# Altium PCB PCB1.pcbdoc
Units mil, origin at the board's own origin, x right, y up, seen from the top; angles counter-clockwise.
Board outline 4979.02 x 1805 mil, 2 copper layers (Top Layer, Bottom Layer); 6 components, 11 nets, 70 pads, 4 vias.
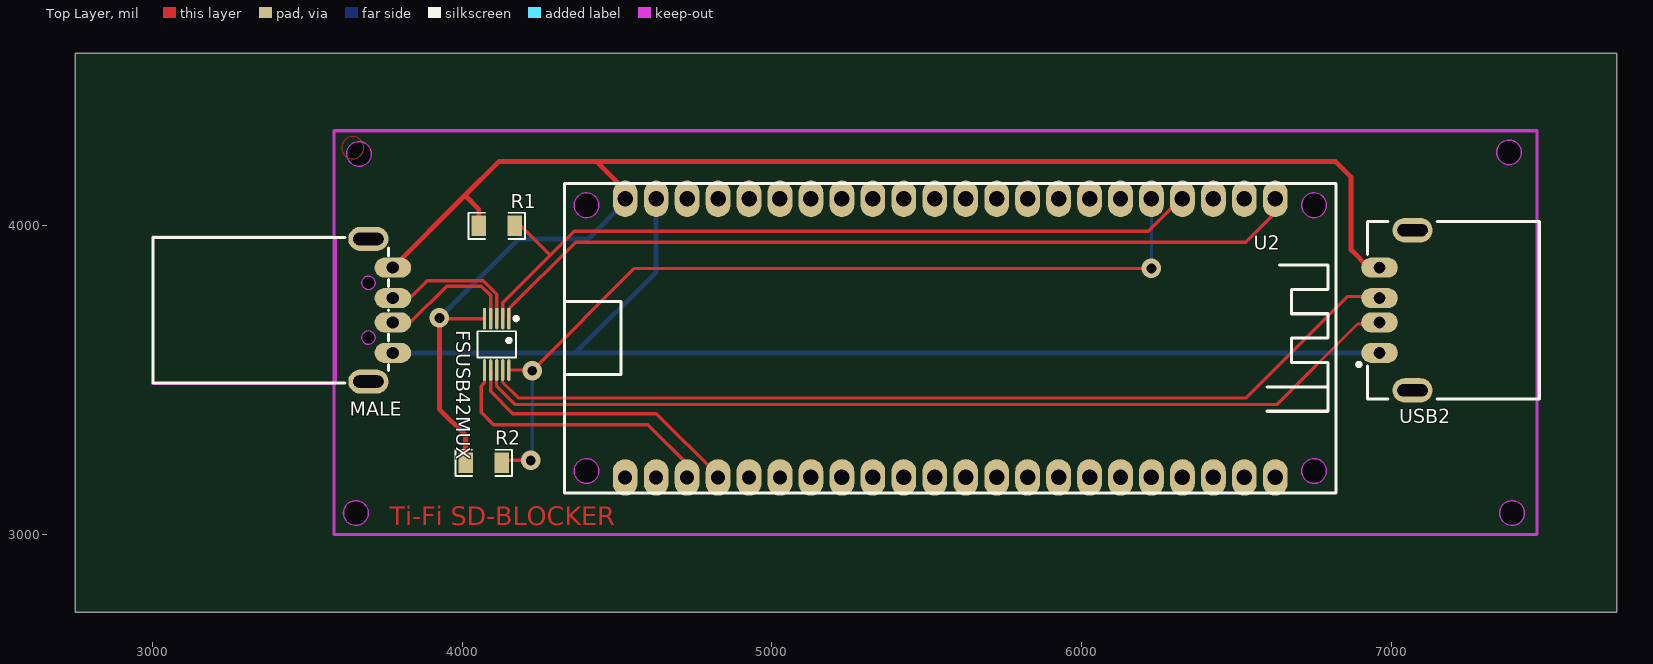
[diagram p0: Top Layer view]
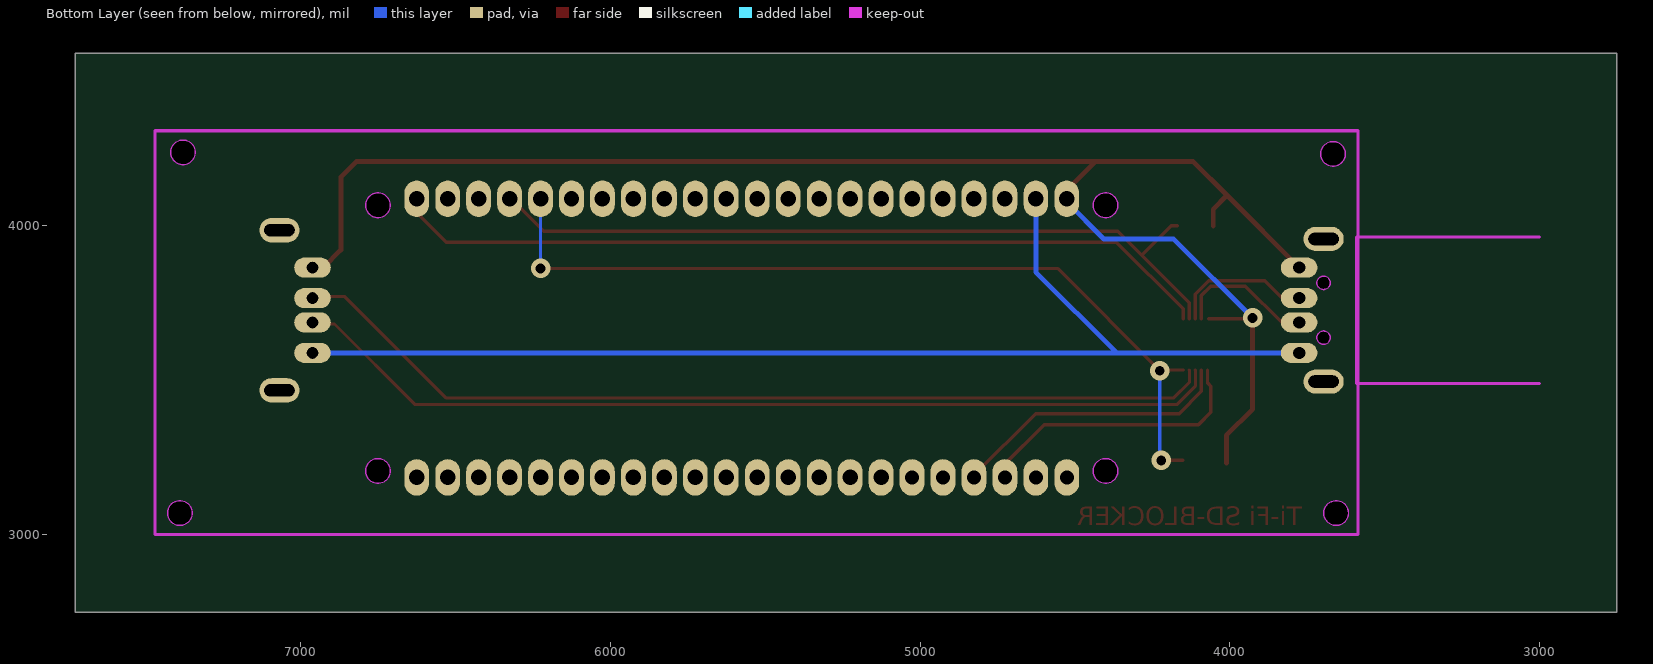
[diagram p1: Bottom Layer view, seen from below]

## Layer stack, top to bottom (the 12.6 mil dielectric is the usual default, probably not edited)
Top Layer: signal copper (thickness not stored)
Dielectric: dielectric 12.6, FR-4, Dk 4.8
Bottom Layer: signal copper (thickness not stored)

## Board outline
7729.02,2750 2750,2750 2750,4555 7729.02,4555
cut-out: 3706.22,4230 cw(c3666.22,4230) 3626.22,4230 cw(c3666.22,4230)
cut-out: 3696.22,3070 cw(c3656.22,3070) 3616.22,3070 cw(c3656.22,3070)
cut-out: 7431.22,3070 cw(c7391.22,3070) 7351.22,3070 cw(c7391.22,3070)
cut-out: 7421.22,4235 cw(c7381.22,4235) 7341.22,4235 cw(c7381.22,4235)

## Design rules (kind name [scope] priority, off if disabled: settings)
BoardOutlineClearance copperThickness1oz [All] p0: genericclearance=10 ignorepadtopadclearanceinfootprint=FALSE except(0: Arc-SplitContinuation Track-SplitContinuation SMDPad-SplitContinuation THPad-SplitContinuation Via-SplitContinuation Fill-SplitContinuation Poly-SplitContinuation Region-SplitContinuation Text-SplitContinuation; 7.9: Track-OutlineEdge SMDPad-OutlineEdge THPad-OutlineEdge Via-OutlineEdge Fill-OutlineEdge Region-OutlineEdge Poly-OutlineEdge Text-OutlineEdge Track-CutoutEdge SMDPad-CutoutEdge THPad-CutoutEdge Via-CutoutEdge Fill-CutoutEdge Region-CutoutEdge)
BoardOutlineClearance copperThickness2oz [All] p0: genericclearance=10 ignorepadtopadclearanceinfootprint=FALSE except(0: Arc-SplitContinuation Track-SplitContinuation SMDPad-SplitContinuation THPad-SplitContinuation Via-SplitContinuation Fill-SplitContinuation Poly-SplitContinuation Region-SplitContinuation Text-SplitContinuation; 6: SMDPad-CutoutEdge THPad-CutoutEdge Via-CutoutEdge Fill-CutoutEdge Region-CutoutEdge; 11.8: Track-OutlineEdge SMDPad-OutlineEdge THPad-OutlineEdge Via-OutlineEdge Fill-OutlineEdge Region-OutlineEdge Poly-OutlineEdge Text-OutlineEdge Track-CutoutEdge)
Clearance copperThickness1oz [(InNet('$1N2926') OR InNet('$1N2770') OR InNet('$1N2815') OR InNet('$1N3095') OR InNet('$1N3264') OR InNet('$1N3111') OR InNet('$1N3122') OR InNet('$1N2863') OR InNet('$1N3580') OR InNet('$1N3681') OR InNet('$1N5589'))] p1: gap=7 ignorepadtopadclearanceinfootprint=FALSE except(7.9: Track-Track Track-SMDPad SMDPad-SMDPad Track-THPad SMDPad-THPad THPad-THPad Track-Via SMDPad-Via THPad-Via Via-Via Track-Fill SMDPad-Fill THPad-Fill Via-Fill Fill-Fill Track-Region SMDPad-Region THPad-Region Via-Region Fill-Region Region-Region Track-Poly SMDPad-Poly THPad-Poly Via-Poly Fill-Poly Region-Poly Poly-Poly Track-Text SMDPad-Text THPad-Text Via-Text Fill-Text Region-Text Poly-Text Text-Text Track-Sheet SMDPad-Sheet THPad-Sheet Via-Sheet Fill-Sheet Region-Sheet Poly-Sheet Text-Sheet Track-Hole SMDPad-Hole THPad-Hole Via-Hole Fill-Hole Region-Hole Poly-Hole Text-Hole Sheet-Hole)
Clearance copperThickness2oz [All] p1: gap=7 ignorepadtopadclearanceinfootprint=FALSE except(6: Track-SMDPad SMDPad-SMDPad Track-THPad SMDPad-THPad THPad-THPad Track-Via SMDPad-Via THPad-Via Via-Via Track-Fill SMDPad-Fill THPad-Fill Via-Fill Fill-Fill SMDPad-Region THPad-Region Via-Region Fill-Region Region-Region Track-Poly SMDPad-Poly THPad-Poly Via-Poly Fill-Poly Poly-Poly Track-Text SMDPad-Text THPad-Text Via-Text Fill-Text Region-Text Poly-Text Text-Text; 6.9: Track-Hole SMDPad-Hole THPad-Hole Via-Hole Fill-Hole Region-Hole Poly-Hole Text-Hole Sheet-Hole; 8: Track-Track; 11.8: Track-Region Region-Poly Track-Sheet SMDPad-Sheet THPad-Sheet Via-Sheet Fill-Sheet Region-Sheet Poly-Sheet Text-Sheet)
DiffPairsRouting differentialPair [All] p1: maxuncoupledlength=10 minlimit=5.9843 maxlimit=5.9843 mostfreqgap=5.9843 toplayer_minwidth=5 toplayer_prefwidth=10 toplayer_maxwidth=100 bottomlayer_minwidth=5 bottomlayer_prefwidth=10 bottomlayer_maxwidth=100
PasteMaskExpansion pasteMaskExpansion [All] p1: expansion=0
PlaneConnect innerPlane [All] p1: planeconnectstyle=Relief reliefexpansion=20 reliefentries=4 reliefconductorwidth=10 reliefairgap=10
PolygonConnect copperRegion [All] p1: connectstyle=Relief reliefentries=4 reliefconductorwidth=10 polygonreliefangle="90 Angle" airgapwidth=10
RoutingVias viaSize [All] p1: viastyle="Through Hole" holewidth=12.0078 minholewidth=11.811 maxholewidth=248.0314 width=24.0158 minwidth=19.685 maxwidth=393.7008
SolderMaskExpansion solderMaskExpansion [All] p1: useseparateexpansions=TRUE expansion=2.0079 expansionbottom=2.0079
Width copperThickness1oz [All] p1: maxlimit=100 minlimit=5 preferedwidth=10
Width copperThickness2oz [All] p1: maxlimit=100 minlimit=8 preferedwidth=10

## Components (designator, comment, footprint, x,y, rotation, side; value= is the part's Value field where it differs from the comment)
FSUSB42MUX "FSUSB42MUX" MSOP-10_L3.0-W3.0-P0.50-LS5.0-BL 4111.22,3615 r180 top
MALE "KH-USB90-AM-4P" USB-A-TH_917-181A202ED60201 3736.22,3725 r270 top
R1 "CR1206J100KP05Z" R1206 4111.49,3997.67 r0 top
R2 "CR1206J100KP05Z" R1206 4069.15,3232.01 r0 top
U2 "ESP32-S3-DEV-KIT-N8R8" COMM-TH_L63.3-W25.4-P2.54-LS22.86 5576.22,3635 r270 top
USB2 "USBR-A-S-S-O-TH" USB-TH_USBR-A-S-S-O-TH 7016.22,3725 r90 top

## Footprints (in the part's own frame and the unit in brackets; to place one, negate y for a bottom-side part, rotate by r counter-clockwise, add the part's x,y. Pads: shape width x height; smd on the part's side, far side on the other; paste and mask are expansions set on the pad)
COMM-TH_L63.3-W25.4-P2.54-LS22.86 [mil]
  oval 118.11x80 hole 50: 1(-450,1050) 2(-450,950) 3(-450,850) 4(-450,750) 5(-450,650) 6(-450,550) 7(-450,450) 8(-450,350) 9(-450,250) 10(-450,150) 11(-450,50) 12(-450,-50) 13(-450,-150) 14(-450,-250) 15(-450,-350) 16(-450,-450) 17(-450,-550) 18(-450,-650) 19(-450,-750) 20(-450,-850) 29(450,-450) 30(450,-350) 31(450,-250) 32(450,-150) 33(450,-50) 34(450,50) 35(450,150) 36(450,250) 37(450,350) 38(450,450) 39(450,550) 40(450,650) 41(450,750) 42(450,850) 43(450,950) 44(450,1050)
  oval 118.11x78.74 hole 50: 21(-450,-950) 22(-450,-1050)
  oval 118.11x80 hole 45: 23(450,-1050) 24(450,-950) 25(450,-850) 26(450,-750) 27(450,-650) 28(450,-550)
  Board Outline Layer circle w1: c429.13,1175.19 r40
  Board Outline Layer circle w1: c429.13,-1175.19 r40
  Board Outline Layer circle w1: c-429.13,-1175.19 r40
  Board Outline Layer circle w1: c-429.13,1175.19 r40
  Board Outline Layer region: 429.13,1215.19 446.49,1211.23 460.41,1200.13 468.13,1184.09 468.13,1166.29 460.41,1150.25 446.49,1139.16 429.13,1135.19 429.13,1135.19 411.78,1139.16 397.86,1150.25 390.14,1166.29 390.14,1184.09 397.86,1200.13 411.78,1211.23 429.13,1215.19
  Board Outline Layer region: 429.13,-1135.19 446.49,-1139.16 460.41,-1150.25 468.13,-1166.29 468.13,-1184.09 460.41,-1200.13 446.49,-1211.23 429.13,-1215.19 429.13,-1215.19 411.78,-1211.23 397.86,-1200.13 390.14,-1184.09 390.14,-1166.29 397.86,-1150.25 411.78,-1139.16 429.13,-1135.19
  Board Outline Layer region: -429.13,-1135.19 -411.78,-1139.16 -397.86,-1150.25 -390.14,-1166.29 -390.14,-1184.09 -397.86,-1200.13 -411.78,-1211.23 -429.13,-1215.19 -429.13,-1215.19 -446.49,-1211.23 -460.41,-1200.13 -468.13,-1184.09 -468.13,-1166.29 -460.41,-1150.25 -446.49,-1139.16 -429.13,-1135.19
  Board Outline Layer region: -429.13,1215.19 -411.78,1211.23 -397.86,1200.13 -390.14,1184.09 -390.14,1166.29 -397.86,1150.25 -411.78,1139.16 -429.13,1135.19 -429.13,1135.19 -446.49,1139.16 -460.41,1150.25 -468.13,1166.29 -468.13,1184.09 -460.41,1200.13 -446.49,1211.23 -429.13,1215.19
  Multi-Layer board cut-out: 429.13,1215.19 446.49,1211.23 460.41,1200.13 468.13,1184.09 468.13,1166.29 460.41,1150.25 446.49,1139.16 429.13,1135.19 429.13,1135.19 411.78,1139.16 397.86,1150.25 390.14,1166.29 390.14,1184.09 397.86,1200.13 411.78,1211.23 429.13,1215.19
  Multi-Layer board cut-out: 429.13,-1135.19 446.49,-1139.16 460.41,-1150.25 468.13,-1166.29 468.13,-1184.09 460.41,-1200.13 446.49,-1211.23 429.13,-1215.19 429.13,-1215.19 411.78,-1211.23 397.86,-1200.13 390.14,-1184.09 390.14,-1166.29 397.86,-1150.25 411.78,-1139.16 429.13,-1135.19
  Multi-Layer board cut-out: -429.13,-1135.19 -411.78,-1139.16 -397.86,-1150.25 -390.14,-1166.29 -390.14,-1184.09 -397.86,-1200.13 -411.78,-1211.23 -429.13,-1215.19 -429.13,-1215.19 -446.49,-1211.23 -460.41,-1200.13 -468.13,-1184.09 -468.13,-1166.29 -460.41,-1150.25 -446.49,-1139.16 -429.13,-1135.19
  Multi-Layer board cut-out: -429.13,1215.19 -411.78,1211.23 -397.86,1200.13 -390.14,1184.09 -390.14,1166.29 -397.86,1150.25 -411.78,1139.16 -429.13,1135.19 -429.13,1135.19 -446.49,1139.16 -460.41,1150.25 -468.13,1166.29 -468.13,1184.09 -460.41,1200.13 -446.49,1211.23 -429.13,1215.19
  silkscreen extent -500,-1246 500,1246
MSOP-10_L3.0-W3.0-P0.50-LS5.0-BL [mm]
  oval 0.28x1.778 smd: 1(-1,-2.11) 2(-0.5,-2.11) 3(0,-2.11) 4(0.5,-2.11) 5(1,-2.11) 6(1,2.11) 7(0.5,2.11) 8(0,2.11) 9(-0.5,2.11) 10(-1,2.11)
  silkscreen extent -1.74,-2.26 1.58,1.07
R1206 [mil]
  rect 47.54x66.97 smd: 1(-58.22,0) 2(58.22,0)
  silkscreen extent -91,-42 91,42
USB-A-TH_917-181A202ED60201 [mm]
  oval 1.651x3 hole 1: 1(3.5,1) 2(1,1) 3(-1,1) 4(-3.5,1)
  oval 2x3.3 hole 1 slot 2.5 at 90 deg: 5(-5.85,-1) 6(5.85,-1)
  Board Outline Layer circle w0.025: c-2.25,-1 r0.55
  Board Outline Layer circle w0.025: c2.25,-1 r0.55
  Board Outline Layer lines w0.254: 6,-3.721 6,-18.7 6,-3.721 ; 6,-3.721 -6,-3.721 ; 6,-3.721 -6,-3.721 ; -6,-3.721 -6,-18.7 -6,-3.721
  Board Outline Layer region: -2.25,-0.45 -2.011,-0.504 -1.82,-0.657 -1.714,-0.878 -1.714,-1.122 -1.82,-1.343 -2.011,-1.496 -2.25,-1.55 -2.25,-1.55 -2.489,-1.496 -2.68,-1.343 -2.786,-1.122 -2.786,-0.878 -2.68,-0.657 -2.489,-0.504 -2.25,-0.45
  Board Outline Layer region: 2.25,-0.45 2.488,-0.504 2.68,-0.657 2.786,-0.878 2.786,-1.122 2.68,-1.343 2.488,-1.496 2.25,-1.55 2.25,-1.55 2.011,-1.496 1.82,-1.343 1.714,-1.122 1.714,-0.878 1.82,-0.657 2.011,-0.504 2.25,-0.45
  Multi-Layer board cut-out: -2.25,-0.45 -2.011,-0.504 -1.82,-0.657 -1.714,-0.878 -1.714,-1.122 -1.82,-1.343 -2.011,-1.496 -2.25,-1.55 -2.25,-1.55 -2.489,-1.496 -2.68,-1.343 -2.786,-1.122 -2.786,-0.878 -2.68,-0.657 -2.489,-0.504 -2.25,-0.45
  Multi-Layer board cut-out: 2.25,-0.45 2.488,-0.504 2.68,-0.657 2.786,-0.878 2.786,-1.122 2.68,-1.343 2.488,-1.496 2.25,-1.55 2.25,-1.55 2.011,-1.496 1.82,-1.343 1.714,-1.122 1.714,-0.878 1.82,-0.657 2.011,-0.504 2.25,-0.45
  silkscreen extent -5.97,-18.67 5.97,0.65
USB-TH_USBR-A-S-S-O-TH [mm]
  oval 1.651x3 hole 0.92 slot 0.925 at 0 deg: 1(-3.5,1.355) 2(-1,1.355) 3(1,1.355) 4(3.5,1.355)
  oval 1.999x3.299 hole 1.001 slot 2.499 at 90 deg: 5(-6.57,-1.355) 6(6.57,-1.355)
  silkscreen extent -7.27,-11.75 7.27,3.2

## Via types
v1: diameter 63, hole 31.5, Top Layer to Bottom Layer, 3 vias
v2: diameter 62.99, hole 31.5, Top Layer to Bottom Layer, 1 vias

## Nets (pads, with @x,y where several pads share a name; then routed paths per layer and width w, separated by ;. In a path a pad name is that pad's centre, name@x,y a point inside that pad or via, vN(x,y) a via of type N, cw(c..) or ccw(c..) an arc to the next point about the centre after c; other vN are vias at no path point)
$1N2770: FSUSB42MUX.3 MALE.3 | length 455.4
  Top Layer w11: MALE.3 3830.6,3764.38 3886.22,3820 4068.26,3820 4111.22,3777.04 FSUSB42MUX.3
$1N2815: FSUSB42MUX.4 MALE.2 | length 451.8
  Top Layer w11: MALE.2 3831.86,3685.64 3949.24,3803.02 4061.22,3803.02 4091.53,3772.71 FSUSB42MUX.4
$1N2863: MALE.1 U2.21 USB2.1 | length 3793.3
  Bottom Layer w15.7: MALE.1 4365.04,3587.2 ; U2.21 4626.22,3848.39 4365.04,3587.2 ; USB2.1 4365.04,3587.2
$1N2926: FSUSB42MUX.1 U2.1 | length 2680.6
  Top Layer w11: FSUSB42MUX.1 4150.59,3729.37 4366.22,3945 6531.22,3945 6626.22,4040 U2.1
$1N3095: FSUSB42MUX.8 USB2.2 | length 3039.5
  Top Layer w10: FSUSB42MUX.8 4109.92,3530.63 4109.91,3481.31 4171.22,3420 6631.22,3420 6891.85,3680.62 6917.88,3680.62 6922.88,3685.62 USB2.2
$1N3111: FSUSB42MUX.7 U2.26 | length 922.9
  Top Layer w11: FSUSB42MUX.7 4091.53,3463 4163.4,3391.13 4627.13,3391.13 4826.22,3192.04 U2.26
$1N3122: FSUSB42MUX.6 U2.25 | length 923.8
  Top Layer w11: FSUSB42MUX.6 4071.85,3490.63 4060.85,3479.63 4060.85,3395.37 4100.85,3355.37 4599.71,3355.37 4731.59,3223.49 4731.59,3190.37 U2.25
$1N3264: FSUSB42MUX.9 USB2.3 | length 3031.7
  Top Layer w10: FSUSB42MUX.9 4129.61,3530.64 4129.61,3493.49 4182.11,3440.98 6530.55,3440.98 6858.42,3768.86 6958.38,3768.86 USB2.3
$1N3580: FSUSB42MUX.2 R1.2 U2.4 | length 2539.6
  Top Layer w11: FSUSB42MUX.2 4130.9,3748.64 4284.58,3902.32 ; R1.2 4189.23,3997.67 4284.58,3902.32 ; U2.4 6321.22,4085 6216.22,3980 4362.26,3980 4284.58,3902.32
$1N3681: FSUSB42MUX.10 R2.2 U2.5 | length 2800.5
  Top Layer w11: FSUSB42MUX.10 4224.29,3531.93 v1(4226.22,3530) 4556.22,3860 v1(6226.22,3860) ; R2.2@4150.88,3240 v1(4221.22,3240)
  Bottom Layer w11: v1(4221.22,3240) 4226.22,3245 v1(4226.22,3530) ; v1(6226.22,3860) U2.5
$1N5589: FSUSB42MUX.5 MALE.4 R1.1 R2.1 U2.22 USB2.4 | length 5294.9
  Top Layer w11: v2(3926.22,3700) 3928.15,3698.07 FSUSB42MUX.5@4068.7,3698.07
  Top Layer w15.7: MALE.4 4008.78,4095.98 ; R1.1 4053.27,4051.49 4008.78,4095.98 ; U2.22 4526.22,4113.13 4434.35,4205 ; USB2.4 6928.43,3862.8 6871.22,3920 6871.22,4155 6821.22,4205 4434.35,4205 ; 4008.78,4095.98 4117.8,4205 4434.35,4205
  Top Layer w15.75: v2(3926.22,3700) 3926.22,3405.34 4010.93,3320.63 R2.1
  Bottom Layer w15.75: v2(3926.22,3700) 4181.22,3955 4406.22,3955 4526.22,4075 U2.22
pads on no net: MALE.5 MALE.6 U2.2 U2.3 U2.6 U2.7 U2.8 U2.9 U2.10 U2.11 U2.12 U2.13 U2.14 U2.15 U2.16 U2.17 U2.18 U2.19 U2.20 U2.23 U2.24 U2.27 U2.28 U2.29 U2.30 U2.31 U2.32 U2.33 U2.34 U2.35 U2.36 U2.37 U2.38 U2.39 U2.40 U2.41 U2.42 U2.43 U2.44 USB2.5 USB2.6

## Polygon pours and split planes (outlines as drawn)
no net on Top Layer (solid, remove dead copper, pour order 0): 3682.28,4250 ccw(c3646.22,4249.6) 3610.17,4250 ccw(c3646.22,4250.4)

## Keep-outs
Board Outline Layer:
  circle w1: c3666.22,4230 r40
  region: 3706.22,4230 cw(c3666.22,4230) 3626.22,4230 cw(c3666.22,4230)
  circle w1: c3656.22,3070 r40
  region: 3696.22,3070 cw(c3656.22,3070) 3616.22,3070 cw(c3656.22,3070)
  circle w1: c7391.22,3070 r40
  region: 7431.22,3070 cw(c7391.22,3070) 7351.22,3070 cw(c7391.22,3070)
  circle w1: c7381.22,4235 r40
  region: 7421.22,4235 cw(c7381.22,4235) 7341.22,4235 cw(c7381.22,4235)
  lines w10: 3586.22,3000 7471.22,3000 7471.22,4305 3586.22,4305 3586.22,3000

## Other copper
Top Layer:
  text "Ti-Fi SD-BLOCKER" at 3766.22,3030 h60

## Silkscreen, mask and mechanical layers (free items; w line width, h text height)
Mechanical Layer:
  circle w1: c3666.22,4230 r40
  circle w1: c3656.22,3070 r40
  circle w1: c7391.22,3070 r40
  circle w1: c7381.22,4235 r40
